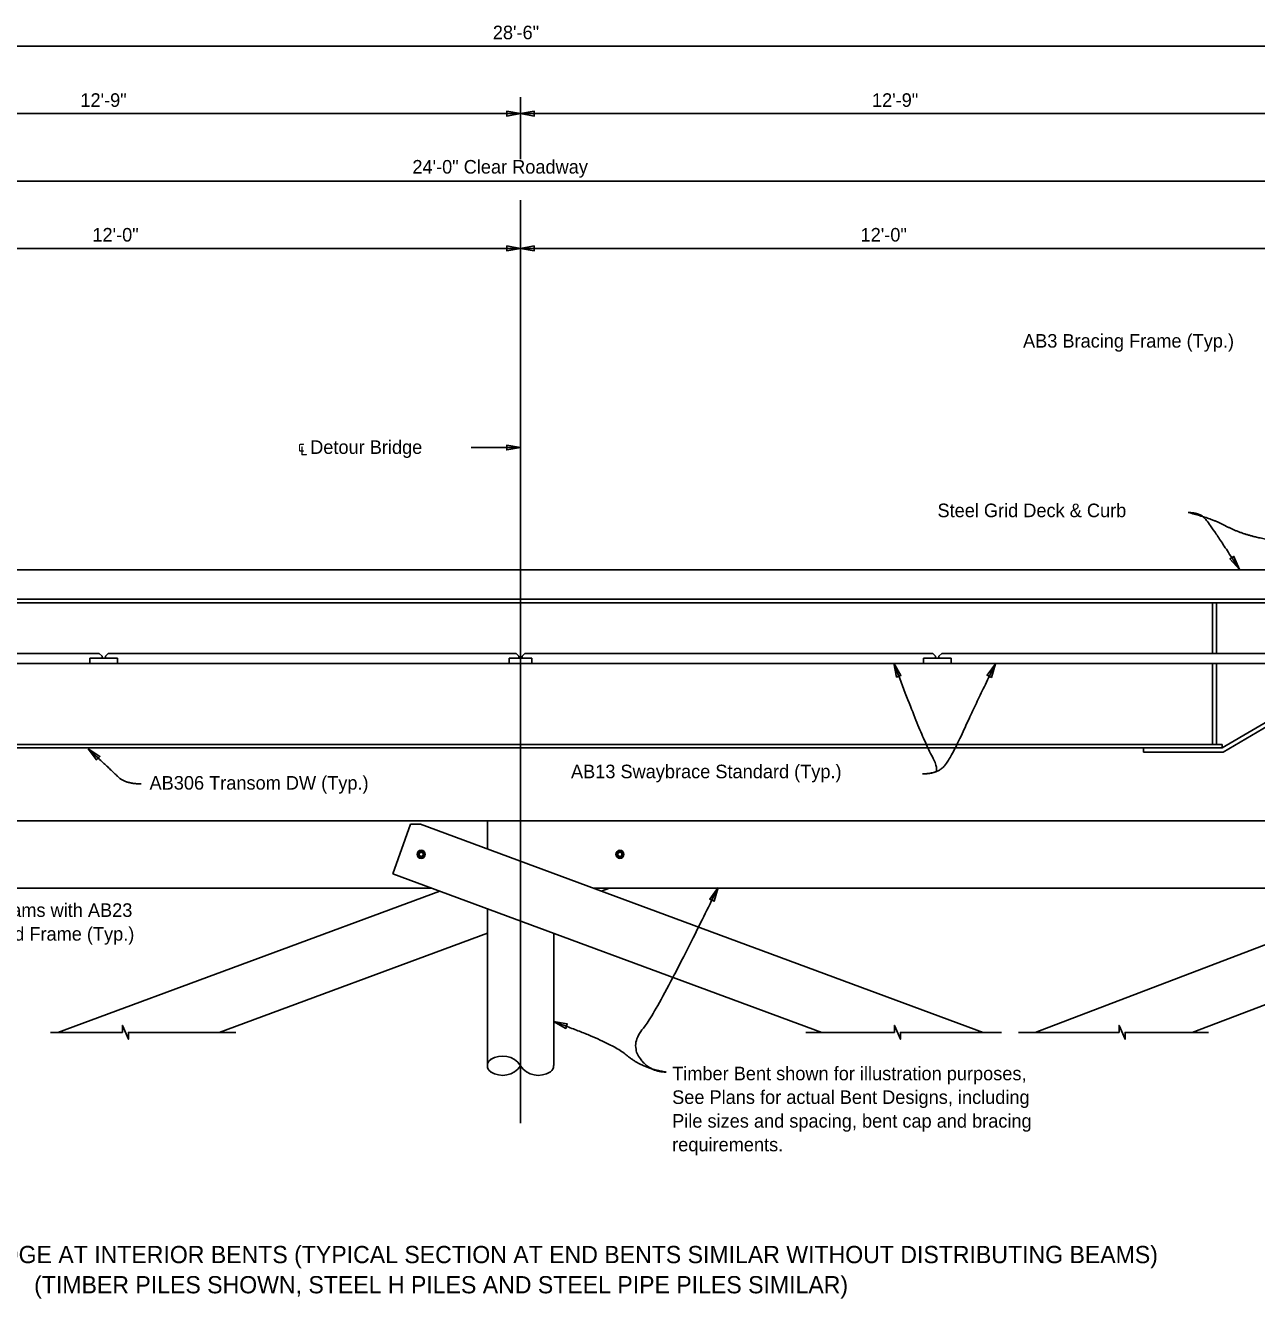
# Model space of a CAD drawing. Extents: x -4.4 to 30.2, y 1.2 to 17.8.
# Drawn here: x 9.03 to 22.97, y 3.33 to 17.76 of the extents above; entities that cross this region are included whole.
import ezdxf

# ---------------------------------------------------------------- set-up
doc = ezdxf.new("R2010")
doc.units = 0
for name, color, linetype in [('CL_Minor', 7, 'Continuous'), ('Dimension', 7, 'Continuous'), ('Miscellaneous', 7, 'Continuous'), ('SteelMisc', 7, 'Continuous'), ('Symbols', 7, 'Continuous'), ('TextStructures', 7, 'Continuous'), ('Wood', 7, 'Continuous')]:
    doc.layers.add(name, color=color, linetype=linetype)

msp = doc.modelspace()

# ---------------------------------------------------------------- linework, layer by layer
at = {"layer": 'CL_Minor'}
for points in [[(14.636, 16.239), (14.636, 16.942)], [(14.636, 5.318), (14.636, 15.774)]]:
    msp.add_lwpolyline(points, dxfattribs=at)
at = {"layer": 'Dimension'}
for p, q in [((3.944, 17.519), (25.327, 17.519)), ((3.944, 16.756), (25.327, 16.756)), ((5.632, 15.993), (23.639, 15.993)), ((5.632, 15.23), (23.639, 15.23)), ((14.076, 12.973), (14.636, 12.973))]:
    msp.add_line(p, q, dxfattribs=at)
for points in [[(14.636, 16.756), (14.479, 16.729), (14.479, 16.783)], [(14.636, 16.756), (14.792, 16.729), (14.792, 16.783)], [(14.479, 15.257), (14.636, 15.23), (14.479, 15.203)], [(14.792, 15.257), (14.636, 15.23), (14.792, 15.203)], [(14.636, 12.973), (14.479, 12.999), (14.479, 12.946)], [(22.778, 11.592), (22.715, 11.74), (22.67, 11.711)], [(18.863, 10.531), (18.894, 10.373), (18.944, 10.392)], [(20.014, 10.523), (19.92, 10.393), (19.968, 10.369)], [(9.737, 9.561), (9.835, 9.434), (9.871, 9.474)], [(16.873, 7.987), (16.779, 7.857), (16.827, 7.833)], [(15.009, 6.469), (15.148, 6.391), (15.165, 6.442)]]:
    msp.add_lwpolyline(points, close=True, dxfattribs=at)
for points in [[(22.199, 12.236), (22.319, 12.236), (22.434, 12.126), (22.778, 11.592)], [(22.199, 12.236), (22.456, 12.174), (22.771, 12.005), (23.147, 11.916), (23.639, 11.832)], [(19.189, 9.276), (19.29, 9.276), (19.38, 9.323), (19.181, 9.691), (18.863, 10.531)], [(19.189, 9.276), (19.348, 9.276), (19.5, 9.43), (19.793, 10.071), (20.014, 10.523)], [(10.338, 9.163), (10.157, 9.163), (10.005, 9.314), (9.737, 9.561)], [(16.287, 5.897), (16.098, 5.897), (15.874, 6.214), (16.185, 6.582), (16.873, 7.987)], [(16.287, 5.897), (16.012, 5.939), (15.668, 6.234), (15.009, 6.469)]]:
    msp.add_open_spline(points, degree=2, dxfattribs=at)
at = {"layer": 'Miscellaneous'}
msp.add_line((23.639, 11.589), (5.632, 11.589), dxfattribs=at)
at = {"layer": 'SteelMisc'}
for p, q in [((5.181, 11.255), (24.091, 11.255)), ((5.181, 11.215), (24.091, 11.215)), ((22.471, 10.64), (22.471, 11.215)), ((22.518, 10.64), (22.518, 11.215)), ((9.865, 10.64), (5.464, 10.64)), ((9.758, 10.587), (10.072, 10.587)), ((9.758, 10.587), (9.758, 10.526)), ((9.865, 10.64), (9.896, 10.608)), ((9.896, 10.608), (9.896, 10.587)), ((9.965, 10.64), (9.934, 10.608)), ((9.934, 10.608), (9.934, 10.587)), ((9.965, 10.64), (14.585, 10.64)), ((10.072, 10.587), (10.072, 10.526)), ((14.506, 10.587), (14.765, 10.587)), ((14.506, 10.587), (14.506, 10.526)), ((14.506, 10.587), (14.506, 10.526)), ((14.765, 10.587), (14.506, 10.587)), ((14.585, 10.64), (14.617, 10.608)), ((14.617, 10.608), (14.617, 10.587)), ((14.686, 10.64), (14.655, 10.608)), ((14.655, 10.608), (14.655, 10.587)), ((19.306, 10.64), (14.686, 10.64)), ((14.765, 10.587), (14.765, 10.526)), ((14.765, 10.587), (14.765, 10.526)), ((19.514, 10.587), (19.199, 10.587)), ((19.199, 10.587), (19.199, 10.526)), ((19.306, 10.64), (19.337, 10.608)), ((19.337, 10.608), (19.337, 10.587)), ((19.407, 10.64), (19.375, 10.608)), ((19.375, 10.608), (19.375, 10.587)), ((19.407, 10.64), (23.808, 10.64)), ((19.514, 10.587), (19.514, 10.526)), ((10.127, 10.526), (5.311, 10.526)), ((9.922, 10.526), (14.765, 10.526)), ((19.349, 10.526), (14.506, 10.526)), ((19.145, 10.526), (23.96, 10.526)), ((22.471, 9.61), (22.471, 10.526)), ((22.518, 9.61), (22.518, 10.526)), ((24.016, 10.412), (22.581, 9.57)), ((24.028, 10.365), (22.593, 9.522)), ((6.691, 9.61), (22.581, 9.61)), ((6.691, 9.57), (22.581, 9.57)), ((21.691, 9.57), (21.691, 9.522)), ((22.593, 9.522), (21.691, 9.522)), ((22.581, 9.61), (22.581, 9.57)), ((3.259, 8.745), (26.032, 8.745))]:
    msp.add_line(p, q, dxfattribs=at)
for points in [[(13.546, 8.385), (13.546, 8.343), (13.51, 8.322), (13.475, 8.343), (13.475, 8.385), (13.51, 8.405)], [(15.797, 8.385), (15.797, 8.343), (15.761, 8.322), (15.726, 8.343), (15.726, 8.385), (15.761, 8.405)]]:
    msp.add_lwpolyline(points, close=True, dxfattribs=at)
for centre, major_axis in [((13.51, 8.364), (0, 0.0467)), ((13.51, 8.364), (0, 0.0362)), ((13.51, 8.364), (0, 0.0238)), ((15.761, 8.364), (0, 0.0467)), ((15.761, 8.364), (0, 0.0362)), ((15.761, 8.364), (0, 0.0238))]:
    msp.add_ellipse(centre, major_axis=major_axis, ratio=0.983193, dxfattribs=at)
at = {"layer": 'Symbols'}
for points in [[(9.311, 6.347), (10.127, 6.347), (10.127, 6.426), (10.195, 6.268), (10.195, 6.347), (11.411, 6.347)], [(17.868, 6.347), (18.871, 6.347), (18.871, 6.426), (18.939, 6.268), (18.939, 6.347), (20.084, 6.347)], [(20.277, 6.347), (21.415, 6.347), (21.415, 6.426), (21.483, 6.268), (21.483, 6.347), (22.427, 6.347)]]:
    msp.add_lwpolyline(points, dxfattribs=at)
at = {"layer": 'Wood'}
for p, q in [((1.506, 8.745), (14.636, 8.745)), ((13.188, 8.144), (13.389, 8.705)), ((13.501, 8.705), (13.389, 8.705)), ((19.877, 6.347), (13.501, 8.705)), ((14.26, 8.425), (14.26, 8.745)), ((27.766, 8.745), (14.636, 8.745)), ((18.047, 6.347), (13.188, 8.144)), ((4.522, 7.982), (13.627, 7.982)), ((9.394, 6.347), (13.721, 7.947)), ((27.766, 7.982), (15.457, 7.982)), ((15.55, 7.947), (15.644, 7.982)), ((14.26, 5.97), (14.26, 7.748)), ((11.224, 6.347), (14.26, 7.47)), ((15.011, 5.97), (15.011, 7.47)), ((23.264, 7.415), (20.463, 6.347)), ((23.264, 6.736), (22.244, 6.347))]:
    msp.add_line(p, q, dxfattribs=at)
for centre, major_axis, start_param, end_param in [((14.432, 5.828), (0, 0.251), 5.311474, 6.859887), ((14.341, 5.97), (0, 0.0817), 0.569243, 1.570759), ((14.341, 5.97), (0, 0.0817), 1.570759, 2.57235), ((14.432, 6.111), (0, 0.251), 2.564849, 4.113262), ((14.839, 6.111), (0, -0.251), 5.311304, 6.859717), ((14.93, 5.97), (0, 0.0817), 3.710836, 4.712426)]:
    msp.add_ellipse(centre, major_axis=major_axis, ratio=0.983193, start_param=start_param, end_param=end_param, dxfattribs=at)

# ---------------------------------------------------------------- texts
at = {"layer": 'Dimension'}
for s, height, p in [('12\'-0"', 0.1538, (9.787, 15.307)), ('12\'-0"', 0.1538, (18.487, 15.307)), ('AB22 Distributing Beams with AB23 ', 0.15385, (6.969, 7.655)), ('Distributing Beam End Frame (Typ.)', 0.15385, (6.969, 7.386))]:
    msp.add_text(s, height=height, dxfattribs=at).set_placement(p)
at = {"layer": 'TextStructures'}
for s, height, p in [('28\'-6"', 0.1538, (14.322, 17.599)), ('12\'-9"', 0.1538, (9.651, 16.833)), ('12\'-9"', 0.1538, (18.616, 16.833)), ('24\'-0" Clear Roadway', 0.15385, (13.411, 16.077)), ('AB3 Bracing Frame (Typ.)', 0.15385, (20.327, 14.105)), ('℄ Detour Bridge', 0.15385, (12.113, 12.901)), ('Steel Grid Deck & Curb', 0.15385, (19.358, 12.184)), ('AB13 Swaybrace Standard (Typ.)', 0.15385, (15.207, 9.226)), ('AB306 Transom DW (Typ.)', 0.15385, (10.434, 9.097)), ('Timber Bent shown for illustration purposes, ', 0.15385, (16.353, 5.804)), ('See Plans for actual Bent Designs, including ', 0.15385, (16.353, 5.536)), ('Pile sizes and spacing, bent cap and bracing ', 0.15385, (16.353, 5.267)), ('requirements.', 0.15385, (16.353, 4.999)), ('TYPICAL SECTION THRU DETOUR BRIDGE AT INTERIOR BENTS (TYPICAL SECTION AT END BENTS SIMILAR WITHOUT DISTRIBUTING BEAMS)', 0.195359, (3.958, 3.732)), ('(TIMBER PILES SHOWN, STEEL H PILES AND STEEL PIPE PILES SIMILAR)', 0.19536, (9.127, 3.39))]:
    msp.add_text(s, height=height, dxfattribs=at).set_placement(p)

doc.saveas('drawing.dxf')
